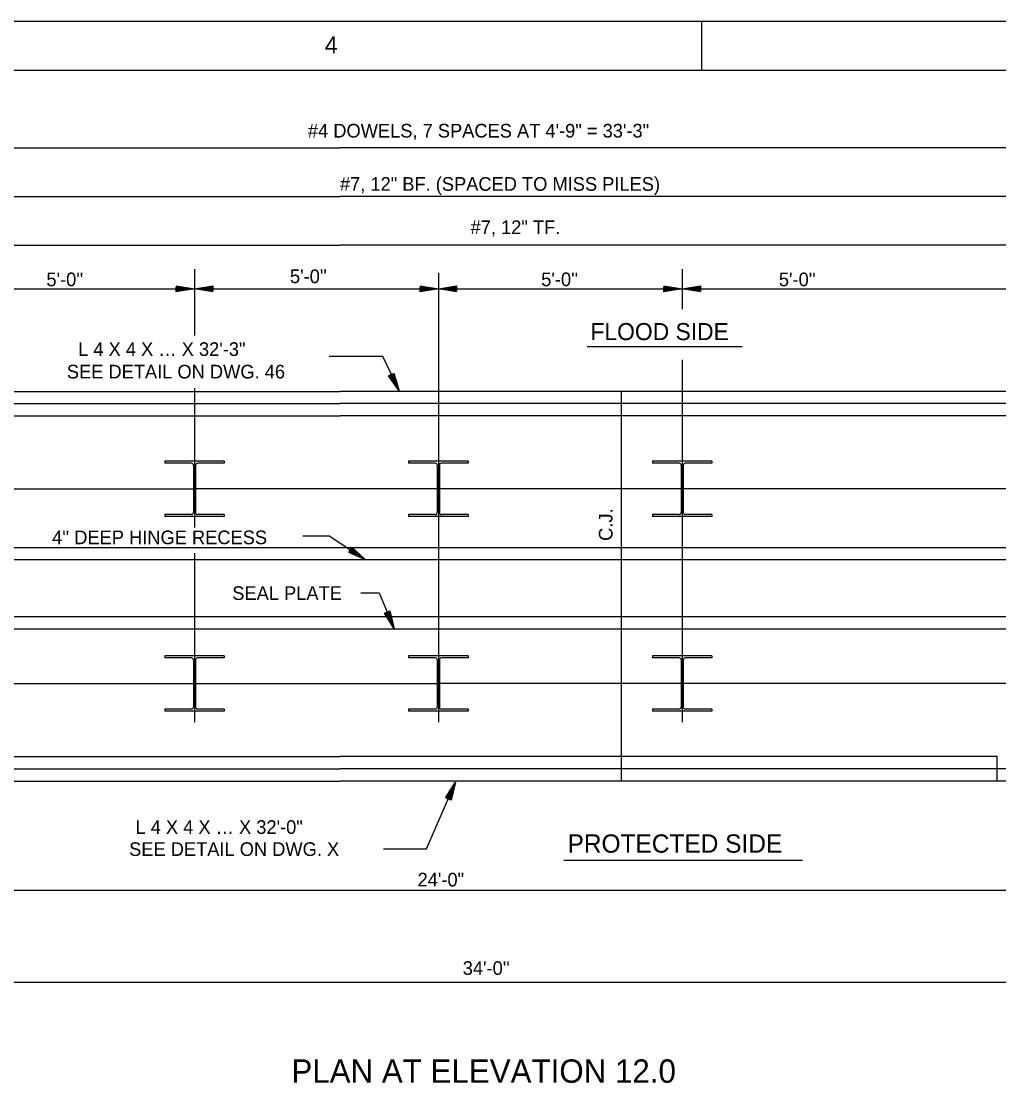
# Model space of a CAD drawing. Extents: x -11983 to -11903, y -13969.5 to -13913.5.
# Drawn here: x -11963.71 to -11943.67, y -13935.3 to -13913.48 of the extents above; entities that cross this region are included whole.
import ezdxf

# ---------------------------------------------------------------- set-up
doc = ezdxf.new("R2010")
doc.units = 0
for name, color, linetype in [('Level 1', 7, 'Continuous'), ('Level 2', 7, 'Continuous'), ('Level 22', 7, 'Continuous'), ('Level 3', 7, 'Continuous'), ('Level 50', 7, 'Continuous'), ('Level 6', 7, 'Continuous')]:
    doc.layers.add(name, color=color, linetype=linetype)

msp = doc.modelspace()

# ---------------------------------------------------------------- linework, layer by layer
at = {"layer": 'Level 1'}
msp.add_line((-11949.762, -13914.481), (-11949.762, -13913.481), dxfattribs=at)
for points in [[(-11983.012, -13913.481), (-11903.012, -13913.481), (-11903.012, -13969.481), (-11983.012, -13969.481)], [(-11980.012, -13914.481), (-11904.012, -13914.481), (-11904.012, -13968.481), (-11980.012, -13968.481)]]:
    msp.add_lwpolyline(points, close=True, dxfattribs=at)
at = {"layer": 'Level 2'}
for p, q in [((-11948.935, -13920.16), (-11952.112, -13920.16)), ((-11972.163, -13921.074), (-11957.178, -13921.074)), ((-11935.387, -13921.074), (-11957.178, -13921.074)), ((-11951.413, -13921.074), (-11951.413, -13929.066)), ((-11966.915, -13921.573), (-11957.178, -13921.573)), ((-11940.43, -13921.573), (-11957.178, -13921.573)), ((-11959.554, -13922.506), (-11960.773, -13922.506)), ((-11960.773, -13922.506), (-11960.773, -13922.548)), ((-11959.554, -13922.506), (-11959.554, -13922.548)), ((-11954.554, -13922.506), (-11955.773, -13922.506)), ((-11955.773, -13922.506), (-11955.773, -13922.548)), ((-11954.554, -13922.506), (-11954.554, -13922.548)), ((-11949.554, -13922.506), (-11950.773, -13922.506)), ((-11950.773, -13922.506), (-11950.773, -13922.548)), ((-11949.554, -13922.506), (-11949.554, -13922.548)), ((-11960.226, -13922.548), (-11960.773, -13922.548)), ((-11960.184, -13922.59), (-11960.184, -13923.558)), ((-11960.142, -13922.59), (-11960.142, -13923.558)), ((-11959.554, -13922.548), (-11960.101, -13922.548)), ((-11955.226, -13922.548), (-11955.773, -13922.548)), ((-11955.184, -13922.59), (-11955.184, -13923.558)), ((-11955.142, -13922.59), (-11955.142, -13923.558)), ((-11954.554, -13922.548), (-11955.101, -13922.548)), ((-11950.226, -13922.548), (-11950.773, -13922.548)), ((-11950.184, -13922.59), (-11950.184, -13923.558)), ((-11950.142, -13922.59), (-11950.142, -13923.558)), ((-11949.554, -13922.548), (-11950.101, -13922.548)), ((-11960.226, -13923.6), (-11960.773, -13923.6)), ((-11960.773, -13923.6), (-11960.773, -13923.642)), ((-11959.554, -13923.6), (-11960.101, -13923.6)), ((-11959.554, -13923.6), (-11959.554, -13923.642)), ((-11955.226, -13923.6), (-11955.773, -13923.6)), ((-11955.773, -13923.6), (-11955.773, -13923.642)), ((-11954.554, -13923.6), (-11955.101, -13923.6)), ((-11954.554, -13923.6), (-11954.554, -13923.642)), ((-11950.226, -13923.6), (-11950.773, -13923.6)), ((-11950.773, -13923.6), (-11950.773, -13923.642)), ((-11949.554, -13923.6), (-11950.101, -13923.6)), ((-11949.554, -13923.6), (-11949.554, -13923.642)), ((-11959.554, -13923.642), (-11960.773, -13923.642)), ((-11954.554, -13923.642), (-11955.773, -13923.642)), ((-11949.554, -13923.642), (-11950.773, -13923.642)), ((-11968.183, -13924.274), (-11942.163, -13924.274)), ((-11968.183, -13924.524), (-11942.122, -13924.524)), ((-11968.183, -13925.691), (-11942.122, -13925.691)), ((-11968.183, -13925.941), (-11942.163, -13925.941)), ((-11959.554, -13926.498), (-11960.773, -13926.498)), ((-11960.773, -13926.498), (-11960.773, -13926.54)), ((-11960.226, -13926.54), (-11960.773, -13926.54)), ((-11960.184, -13926.582), (-11960.184, -13927.55)), ((-11960.142, -13926.582), (-11960.142, -13927.55)), ((-11959.554, -13926.54), (-11960.101, -13926.54)), ((-11959.554, -13926.498), (-11959.554, -13926.54)), ((-11954.554, -13926.498), (-11955.773, -13926.498)), ((-11955.773, -13926.498), (-11955.773, -13926.54)), ((-11955.226, -13926.54), (-11955.773, -13926.54)), ((-11955.184, -13926.582), (-11955.184, -13927.55)), ((-11955.142, -13926.582), (-11955.142, -13927.55)), ((-11954.554, -13926.54), (-11955.101, -13926.54)), ((-11954.554, -13926.498), (-11954.554, -13926.54)), ((-11949.554, -13926.498), (-11950.773, -13926.498)), ((-11950.773, -13926.498), (-11950.773, -13926.54)), ((-11950.226, -13926.54), (-11950.773, -13926.54)), ((-11950.184, -13926.582), (-11950.184, -13927.55)), ((-11950.142, -13926.582), (-11950.142, -13927.55)), ((-11949.554, -13926.54), (-11950.101, -13926.54)), ((-11949.554, -13926.498), (-11949.554, -13926.54)), ((-11960.226, -13927.592), (-11960.773, -13927.592)), ((-11960.773, -13927.592), (-11960.773, -13927.634)), ((-11959.554, -13927.634), (-11960.773, -13927.634)), ((-11959.554, -13927.592), (-11960.101, -13927.592)), ((-11959.554, -13927.592), (-11959.554, -13927.634)), ((-11955.226, -13927.592), (-11955.773, -13927.592)), ((-11955.773, -13927.592), (-11955.773, -13927.634)), ((-11954.554, -13927.634), (-11955.773, -13927.634)), ((-11954.554, -13927.592), (-11955.101, -13927.592)), ((-11954.554, -13927.592), (-11954.554, -13927.634)), ((-11950.226, -13927.592), (-11950.773, -13927.592)), ((-11950.773, -13927.592), (-11950.773, -13927.634)), ((-11949.554, -13927.634), (-11950.773, -13927.634)), ((-11949.554, -13927.592), (-11950.101, -13927.592)), ((-11949.554, -13927.592), (-11949.554, -13927.634)), ((-11969.243, -13928.566), (-11957.178, -13928.566)), ((-11943.705, -13928.566), (-11957.178, -13928.566)), ((-11943.705, -13929.066), (-11943.705, -13928.566)), ((-11972.163, -13929.066), (-11957.178, -13929.066)), ((-11935.387, -13929.066), (-11957.178, -13929.066)), ((-11947.696, -13930.698), (-11952.592, -13930.698))]:
    msp.add_line(p, q, dxfattribs=at)
for centre, start, end in [((-11960.226, -13922.59), 0, 90), ((-11960.101, -13922.59), 90, 180), ((-11955.226, -13922.59), 0, 90), ((-11955.101, -13922.59), 90, 180), ((-11950.226, -13922.59), 0, 90), ((-11950.101, -13922.59), 90, 180), ((-11960.226, -13923.558), 270, 0), ((-11960.101, -13923.558), 180, 270), ((-11955.226, -13923.558), 270, 0), ((-11955.101, -13923.558), 180, 270), ((-11950.226, -13923.558), 270, 0), ((-11950.101, -13923.558), 180, 270), ((-11960.226, -13926.582), 0, 90), ((-11960.101, -13926.582), 90, 180), ((-11955.226, -13926.582), 0, 90), ((-11955.101, -13926.582), 90, 180), ((-11950.226, -13926.582), 0, 90), ((-11950.101, -13926.582), 90, 180), ((-11960.226, -13927.55), 270, 0), ((-11960.101, -13927.55), 180, 270), ((-11955.226, -13927.55), 270, 0), ((-11955.101, -13927.55), 180, 270), ((-11950.226, -13927.55), 270, 0), ((-11950.101, -13927.55), 180, 270)]:
    msp.add_arc(centre, 0.0417, start, end, dxfattribs=at)
at = {"layer": 'Level 22'}
for p, q in [((-11960.163, -13922.385), (-11960.163, -13923.074)), ((-11955.163, -13922.438), (-11955.163, -13923.074)), ((-11950.163, -13922.346), (-11950.163, -13923.074)), ((-11960.163, -13923.074), (-11960.163, -13923.865)), ((-11955.163, -13923.074), (-11955.163, -13923.865)), ((-11950.163, -13923.082), (-11950.163, -13923.72)), ((-11960.163, -13926.377), (-11960.163, -13927.066)), ((-11955.163, -13926.377), (-11955.163, -13927.066)), ((-11950.163, -13926.377), (-11950.163, -13927.066)), ((-11960.163, -13927.066), (-11960.163, -13927.857)), ((-11955.163, -13927.066), (-11955.163, -13927.857)), ((-11950.163, -13927.066), (-11950.163, -13927.857))]:
    msp.add_line(p, q, dxfattribs=at)
at = {"layer": 'Level 3'}
for p, q in [((-11971.677, -13916.074), (-11957.178, -13916.074)), ((-11938.427, -13916.074), (-11957.178, -13916.074)), ((-11971.914, -13917.074), (-11957.178, -13917.074)), ((-11938.163, -13917.074), (-11957.178, -13917.074)), ((-11971.914, -13918.074), (-11957.178, -13918.074)), ((-11937.693, -13918.074), (-11957.178, -13918.074)), ((-11960.163, -13918.569), (-11960.163, -13919.925)), ((-11950.163, -13918.569), (-11950.163, -13919.385)), ((-11955.163, -13918.638), (-11955.163, -13923.074)), ((-11965.163, -13918.971), (-11960.163, -13918.971)), ((-11960.163, -13918.971), (-11955.163, -13918.971)), ((-11955.163, -13918.971), (-11950.163, -13918.971)), ((-11950.163, -13918.971), (-11942.887, -13918.971)), ((-11950.163, -13920.428), (-11950.163, -13923.074)), ((-11956.01, -13920.971), (-11956.01, -13920.971)), ((-11960.163, -13921.007), (-11960.163, -13923.798)), ((-11955.964, -13921.064), (-11955.964, -13921.064)), ((-11971.331, -13923.074), (-11960.163, -13923.074)), ((-11950.163, -13923.074), (-11960.163, -13923.074)), ((-11955.163, -13923.074), (-11955.163, -13927.066)), ((-11935.294, -13923.074), (-11950.163, -13923.074)), ((-11950.163, -13923.074), (-11950.163, -13925.691)), ((-11960.163, -13924.392), (-11960.163, -13927.066)), ((-11956.748, -13924.467), (-11956.748, -13924.467)), ((-11956.661, -13924.524), (-11956.661, -13924.524)), ((-11950.163, -13925.691), (-11950.163, -13927.066)), ((-11956.108, -13925.845), (-11956.108, -13925.845)), ((-11956.068, -13925.941), (-11956.068, -13925.941)), ((-11971.099, -13927.066), (-11955.163, -13927.066)), ((-11935.294, -13927.066), (-11955.163, -13927.066)), ((-11954.852, -13929.187), (-11954.852, -13929.187)), ((-11954.81, -13929.092), (-11954.81, -13929.092)), ((-11967.163, -13931.302), (-11943.125, -13931.302)), ((-11938.163, -13933.196), (-11972.163, -13933.196))]:
    msp.add_line(p, q, dxfattribs=at)
for points in [[(-11957.404, -13920.353), (-11956.311, -13920.353), (-11955.964, -13921.064)], [(-11956.073, -13920.701), (-11955.964, -13921.064), (-11956.184, -13920.755), (-11956.089, -13920.709), (-11956.01, -13920.971), (-11956.159, -13920.761), (-11956.098, -13920.731), (-11956.054, -13920.881), (-11956.134, -13920.766), (-11956.109, -13920.754), (-11956.099, -13920.787)], [(-11957.938, -13924.037), (-11957.4, -13924.037), (-11956.661, -13924.524)], [(-11957.007, -13924.37), (-11956.661, -13924.524), (-11956.939, -13924.267), (-11956.997, -13924.355), (-11956.748, -13924.467), (-11956.936, -13924.292), (-11956.974, -13924.349), (-11956.831, -13924.412), (-11956.934, -13924.318), (-11956.95, -13924.341), (-11956.918, -13924.355)], [(-11956.753, -13925.209), (-11956.374, -13925.209), (-11956.068, -13925.941)], [(-11956.155, -13925.572), (-11956.068, -13925.941), (-11956.27, -13925.62), (-11956.172, -13925.579), (-11956.108, -13925.845), (-11956.245, -13925.627), (-11956.182, -13925.601), (-11956.147, -13925.753), (-11956.22, -13925.634), (-11956.194, -13925.623), (-11956.187, -13925.657)], [(-11956.285, -13930.458), (-11955.407, -13930.458), (-11954.81, -13929.092)], [(-11955.017, -13929.41), (-11954.81, -13929.092), (-11954.903, -13929.459), (-11955.001, -13929.417), (-11954.852, -13929.187), (-11954.915, -13929.437), (-11954.978, -13929.41), (-11954.892, -13929.279), (-11954.927, -13929.414), (-11954.953, -13929.403), (-11954.934, -13929.374)]]:
    msp.add_lwpolyline(points, dxfattribs=at)
at = {"layer": 'Level 50'}
for p, q in [((-11960.267, -13918.971), (-11960.267, -13918.971)), ((-11960.163, -13918.971), (-11960.163, -13918.971)), ((-11960.163, -13918.971), (-11960.163, -13918.971)), ((-11960.059, -13918.971), (-11960.059, -13918.971)), ((-11955.267, -13918.971), (-11955.267, -13918.971)), ((-11955.163, -13918.971), (-11955.163, -13918.971)), ((-11955.163, -13918.971), (-11955.163, -13918.971)), ((-11955.059, -13918.971), (-11955.059, -13918.971)), ((-11950.267, -13918.971), (-11950.267, -13918.971)), ((-11950.163, -13918.971), (-11950.163, -13918.971)), ((-11950.163, -13918.971), (-11950.163, -13918.971)), ((-11950.059, -13918.971), (-11950.059, -13918.971))]:
    msp.add_line(p, q, dxfattribs=at)
for points in [[(-11960.537, -13918.909), (-11960.163, -13918.971), (-11960.537, -13919.033), (-11960.537, -13918.927), (-11960.267, -13918.971), (-11960.521, -13919.013), (-11960.521, -13918.945), (-11960.367, -13918.971), (-11960.505, -13918.993), (-11960.505, -13918.965), (-11960.471, -13918.971)], [(-11959.789, -13919.033), (-11960.163, -13918.971), (-11959.789, -13918.909), (-11959.789, -13919.015), (-11960.059, -13918.971), (-11959.805, -13918.929), (-11959.805, -13918.997), (-11959.959, -13918.971), (-11959.821, -13918.949), (-11959.821, -13918.977), (-11959.855, -13918.971)], [(-11955.537, -13918.909), (-11955.163, -13918.971), (-11955.537, -13919.033), (-11955.537, -13918.927), (-11955.267, -13918.971), (-11955.521, -13919.013), (-11955.521, -13918.945), (-11955.367, -13918.971), (-11955.505, -13918.993), (-11955.505, -13918.965), (-11955.471, -13918.971)], [(-11954.789, -13919.033), (-11955.163, -13918.971), (-11954.789, -13918.909), (-11954.789, -13919.015), (-11955.059, -13918.971), (-11954.805, -13918.929), (-11954.805, -13918.997), (-11954.959, -13918.971), (-11954.821, -13918.949), (-11954.821, -13918.977), (-11954.855, -13918.971)], [(-11950.537, -13918.909), (-11950.163, -13918.971), (-11950.537, -13919.033), (-11950.537, -13918.927), (-11950.267, -13918.971), (-11950.521, -13919.013), (-11950.521, -13918.945), (-11950.367, -13918.971), (-11950.505, -13918.993), (-11950.505, -13918.965), (-11950.471, -13918.971)], [(-11949.789, -13919.033), (-11950.163, -13918.971), (-11949.789, -13918.909), (-11949.789, -13919.015), (-11950.059, -13918.971), (-11949.805, -13918.929), (-11949.805, -13918.997), (-11949.959, -13918.971), (-11949.821, -13918.949), (-11949.821, -13918.977), (-11949.855, -13918.971)]]:
    msp.add_lwpolyline(points, dxfattribs=at)
at = {"layer": 'Level 6'}
for p, q in [((-11972.035, -13921.324), (-11957.178, -13921.324)), ((-11935.499, -13921.324), (-11957.178, -13921.324)), ((-11972.035, -13928.816), (-11957.178, -13928.816)), ((-11935.499, -13928.816), (-11957.178, -13928.816))]:
    msp.add_line(p, q, dxfattribs=at)

# ---------------------------------------------------------------- texts
at = {"layer": 'Level 1'}
msp.add_text('4', height=0.351, dxfattribs=at).set_placement((-11957.489, -13914.142))
at = {"layer": 'Level 2'}
for s, height, p in [('FLOOD SIDE', 0.3503, (-11952.044, -13920.022)), ('PROTECTED SIDE', 0.375, (-11952.514, -13930.536)), ('PLAN AT ELEVATION 12.0', 0.48, (-11958.176, -13935.256))]:
    msp.add_text(s, height=height, dxfattribs=at).set_placement(p)
at = {"layer": 'Level 3'}
for s, p in [('#4 DOWELS, 7 SPACES AT 4\'-9" = 33\'-3"', (-11957.837, -13915.866)), ('#7, 12" BF. (SPACED TO MISS PILES)', (-11957.18, -13916.958)), ('#7, 12" TF.', (-11954.502, -13917.845)), ("5'-0''", (-11958.205, -13918.853)), ("5'-0''", (-11963.199, -13918.916)), ("5'-0''", (-11953.054, -13918.915)), ("5'-0''", (-11948.181, -13918.917)), ('L 4 X 4 X … X 32\'-3"', (-11962.548, -13920.346)), ('SEE DETAIL ON DWG. 46', (-11962.78, -13920.808)), ("4'' DEEP HINGE RECESS ", (-11963.083, -13924.208)), ('SEAL PLATE', (-11959.388, -13925.352)), ('L 4 X 4 X … X 32\'-0"', (-11961.373, -13930.15)), ('SEE DETAIL ON DWG. X', (-11961.503, -13930.603)), ('24\'-0"', (-11955.589, -13931.228)), ("34'-0''", (-11954.663, -13933.043))]:
    msp.add_text(s, height=0.28, dxfattribs=at).set_placement(p)
msp.add_text('C.J.', height=0.28, rotation=90, dxfattribs=at).set_placement((-11951.592, -13924.139))

doc.saveas('drawing.dxf')
